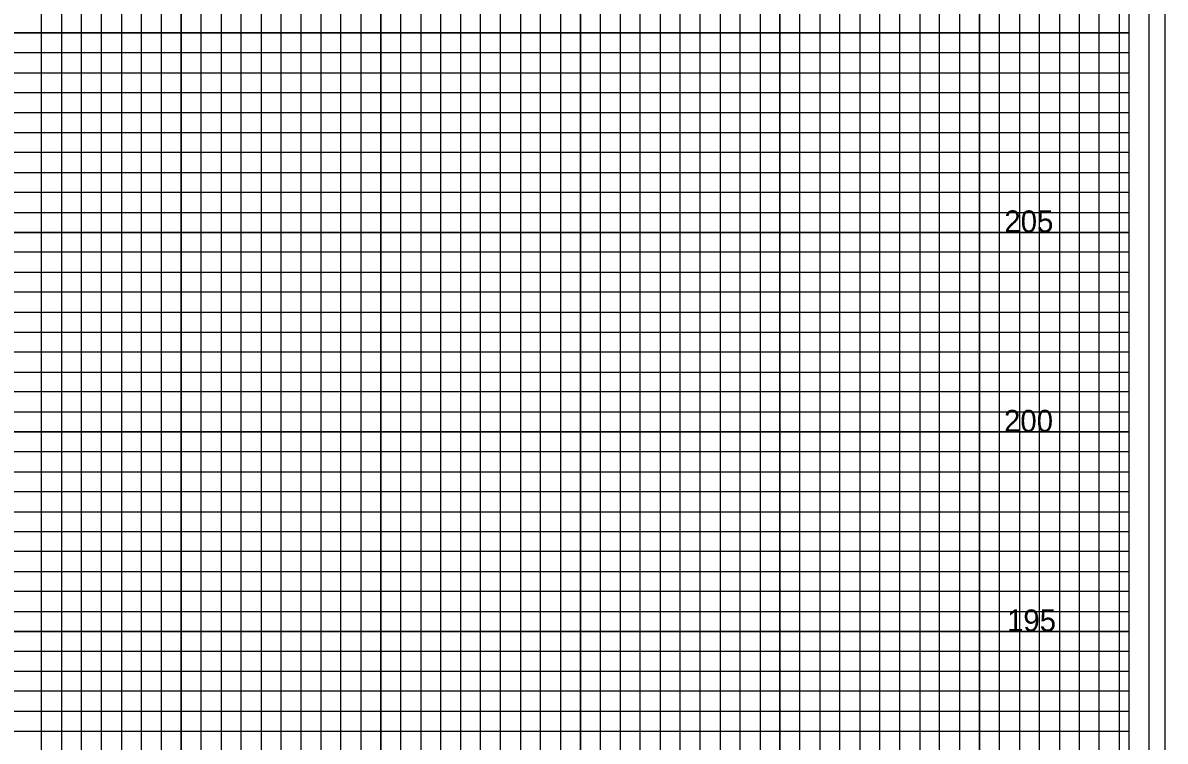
# Model space of a CAD drawing. Extents: x -4 to 103, y -2 to 209.
# Drawn here: x 74.78 to 103.4, y 173.9 to 191.9 of the extents above; entities that cross this region are included whole.
import ezdxf

# ---------------------------------------------------------------- set-up
doc = ezdxf.new("R2010")
doc.units = 0
for name, color, linetype in [('Exist XS Ground Line', 7, 'Continuous'), ('Old_Level_10', 7, 'Continuous'), ('Old_Level_5', 7, 'Continuous'), ('Old_Level_8', 7, 'Continuous'), ('Prop XS Dump Level', 7, 'Continuous'), ('Prop XS Finish Grade', 7, 'Continuous'), ('Prop XS Label Text', 7, 'Continuous')]:
    doc.layers.add(name, color=color, linetype=linetype)

msp = doc.modelspace()

# ---------------------------------------------------------------- linework, layer by layer
at = {"layer": 'Exist XS Ground Line'}
msp.add_lwpolyline([(103, 207.65), (-2.8, 207.65), (-2.8, 140.65), (103, 140.65)], close=True, dxfattribs=at)
at = {"layer": 'Old_Level_10'}
for p, q in [((91.25, 141.65), (91.25, 205.075)), ((93.75, 141.65), (93.75, 205.075)), ((96.25, 141.65), (96.25, 205.075)), ((98.75, 141.65), (98.75, 205.075)), ((101.25, 141.65), (101.25, 205.075)), ((76.25, 141.65), (76.25, 203.65)), ((78.75, 141.65), (78.75, 203.65)), ((81.25, 141.65), (81.25, 203.65)), ((83.75, 141.65), (83.75, 203.65)), ((86.25, 141.65), (86.25, 203.65)), ((88.75, 141.65), (88.75, 203.65)), ((0, 191.65), (102.5, 191.65)), ((0, 189.15), (102.5, 189.15)), ((0, 186.65), (102.5, 186.65)), ((0, 184.15), (102.5, 184.15)), ((0, 181.65), (102.5, 181.65)), ((0, 179.15), (102.5, 179.15)), ((0, 176.65), (102.5, 176.65)), ((0, 174.15), (102.5, 174.15))]:
    msp.add_line(p, q, dxfattribs=at)
at = {"layer": 'Old_Level_5'}
msp.add_lwpolyline([(103.4, 209.05), (-3.5, 209.05), (-3.5, 139.225), (103.4, 139.225)], close=True, dxfattribs=at)
at = {"layer": 'Old_Level_8'}
for points in [[(91.25, 141.65), (91.25, 205.075), (93.75, 205.075), (93.75, 141.65)], [(96.25, 141.65), (96.25, 205.075), (98.75, 205.075), (98.75, 141.65)], [(101.25, 141.65), (101.25, 205.075)], [(76.25, 141.65), (76.25, 203.65), (78.75, 203.65), (78.75, 141.65)], [(81.25, 141.65), (81.25, 203.65), (83.75, 203.65), (83.75, 141.65)], [(86.25, 141.65), (86.25, 203.65), (88.75, 203.65), (88.75, 141.65)], [(0, 189.15), (102.5, 189.15), (102.5, 191.65), (0, 191.65)], [(0, 184.15), (102.5, 184.15), (102.5, 186.65), (0, 186.65)], [(0, 179.15), (102.5, 179.15), (102.5, 181.65), (0, 181.65)], [(0, 174.15), (102.5, 174.15), (102.5, 176.65), (0, 176.65)]]:
    msp.add_lwpolyline(points, dxfattribs=at)
at = {"layer": 'Prop XS Dump Level'}
msp.add_lwpolyline([(102.5, 206.65), (0, 206.65), (0, 141.65), (102.5, 141.65)], close=True, dxfattribs=at)
at = {"layer": 'Prop XS Finish Grade'}
for points in [[(90.25, 141.65), (90.25, 205.075), (90.75, 205.075), (90.75, 141.65)], [(91.75, 141.65), (91.75, 205.075), (92.25, 205.075), (92.25, 141.65)], [(92.75, 141.65), (92.75, 205.075), (93.25, 205.075), (93.25, 141.65)], [(94.25, 141.65), (94.25, 205.075), (94.75, 205.075), (94.75, 141.65)], [(95.25, 141.65), (95.25, 205.075), (95.75, 205.075), (95.75, 141.65)], [(96.75, 141.65), (96.75, 205.075), (97.25, 205.075), (97.25, 141.65)], [(97.75, 141.65), (97.75, 205.075), (98.25, 205.075), (98.25, 141.65)], [(99.25, 141.65), (99.25, 205.075), (99.75, 205.075), (99.75, 141.65)], [(100.25, 141.65), (100.25, 205.075)], [(100.25, 205.075), (100.75, 205.075), (100.75, 141.65), (101.75, 141.65), (101.75, 205.075), (102.25, 205.075), (102.25, 141.65)], [(75.25, 141.65), (75.25, 203.65), (75.75, 203.65), (75.75, 141.65)], [(76.75, 141.65), (76.75, 203.65), (77.25, 203.65), (77.25, 141.65)], [(77.75, 141.65), (77.75, 203.65), (78.25, 203.65), (78.25, 141.65)], [(79.25, 141.65), (79.25, 203.65), (79.75, 203.65), (79.75, 141.65)], [(80.25, 141.65), (80.25, 203.65), (80.75, 203.65), (80.75, 141.65)], [(81.75, 141.65), (81.75, 203.65), (82.25, 203.65), (82.25, 141.65)], [(82.75, 141.65), (82.75, 203.65), (83.25, 203.65), (83.25, 141.65)], [(84.25, 141.65), (84.25, 203.65), (84.75, 203.65), (84.75, 141.65)], [(85.25, 141.65), (85.25, 203.65), (85.75, 203.65), (85.75, 141.65)], [(86.75, 141.65), (86.75, 203.65), (87.25, 203.65), (87.25, 141.65)], [(87.75, 141.65), (87.75, 203.65), (88.25, 203.65), (88.25, 141.65)], [(89.25, 141.65), (89.25, 203.65), (89.75, 203.65), (89.75, 141.65)], [(0, 190.65), (102.5, 190.65), (102.5, 191.15), (0, 191.15)], [(0, 189.65), (102.5, 189.65), (102.5, 190.15), (0, 190.15)], [(0, 188.15), (102.5, 188.15), (102.5, 188.65), (0, 188.65)], [(0, 187.15), (102.5, 187.15), (102.5, 187.65), (0, 187.65)], [(0, 185.65), (102.5, 185.65), (102.5, 186.15), (0, 186.15)], [(0, 184.65), (102.5, 184.65), (102.5, 185.15), (0, 185.15)], [(0, 183.15), (102.5, 183.15), (102.5, 183.65), (0, 183.65)], [(0, 182.15), (102.5, 182.15), (102.5, 182.65), (0, 182.65)], [(0, 180.65), (102.5, 180.65), (102.5, 181.15), (0, 181.15)], [(0, 179.65), (102.5, 179.65), (102.5, 180.15), (0, 180.15)], [(0, 178.15), (102.5, 178.15), (102.5, 178.65), (0, 178.65)], [(0, 177.15), (102.5, 177.15), (102.5, 177.65), (0, 177.65)], [(0, 175.65), (102.5, 175.65), (102.5, 176.15), (0, 176.15)], [(0, 174.65), (102.5, 174.65), (102.5, 175.15), (0, 175.15)]]:
    msp.add_lwpolyline(points, dxfattribs=at)

# ---------------------------------------------------------------- texts
at = {"layer": 'Prop XS Label Text'}
for s, p in [('205', (99.3724, 186.65)), ('200', (99.3638, 181.65)), ('195', (99.4383, 176.65))]:
    msp.add_text(s, height=0.55, dxfattribs=at).set_placement(p)

doc.saveas('drawing.dxf')
